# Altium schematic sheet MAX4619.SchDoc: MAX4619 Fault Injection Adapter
size B; Engineer: Joe Grand; Revision: A; SheetNumber: 1; SheetTotal: 1; PageSetup: Record=PageOptions¦CenterHorizontal=True¦CenterVertical=True¦PrintScale=0.70¦XCorrection=1.00¦YCorrection=1.00¦PrintKind=0¦BorderSize=5000000¦LeftOffset=0¦BottomOffset=0¦Orientation=2¦PaperLength=1000¦PaperWidth=1000¦Scale=100¦PaperSource=7¦PrintQuality=-4¦MediaType=1¦DitherType=10¦PrintScaleMode=1¦PaperKind=Letter
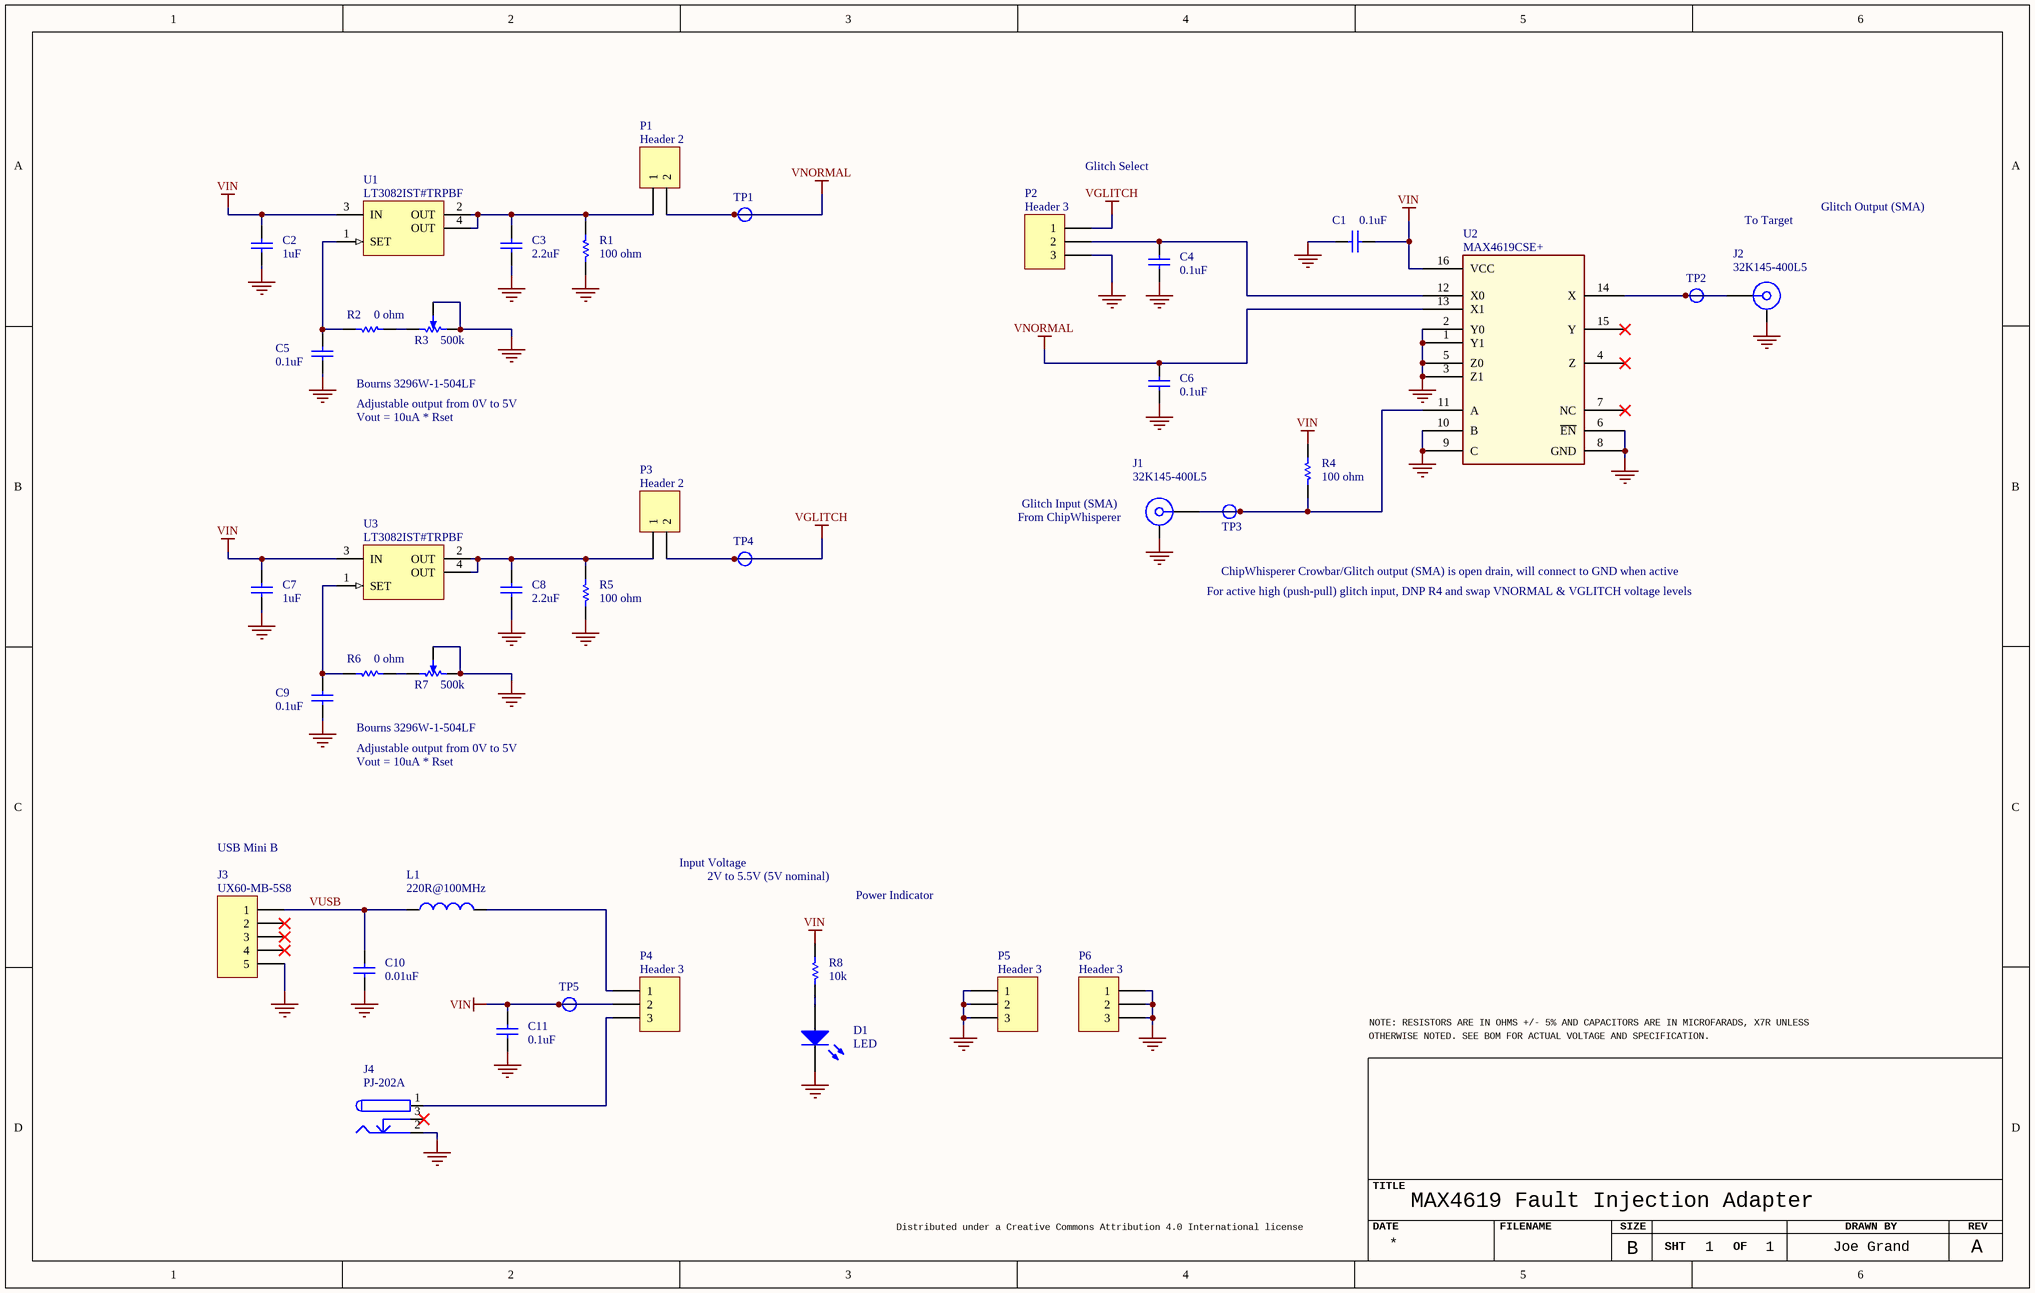
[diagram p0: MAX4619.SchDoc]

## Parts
*  Page Size: B  RevCode: A  Page Count: 1  OrgName: Joe Grand  Title: MAX4619 Fault Injection Adapter  (hidden comment: GIS Title Block)  (graphical)
C1  value 0.1uF  [CC2012-0805]  (hidden comment: Cap)
C2  value 1uF  [CC2012-0805]  (hidden comment: Cap)
C3  value 2.2uF  [CC2012-0805]  (hidden comment: Cap)
C4  value 0.1uF  [CC2012-0805]  (hidden comment: Cap)
C5  value 0.1uF  [CC2012-0805]  (hidden comment: Cap)
C6  value 0.1uF  [CC2012-0805]  (hidden comment: Cap)
C7  value 1uF  [CC2012-0805]  (hidden comment: Cap)
C8  value 2.2uF  [CC2012-0805]  (hidden comment: Cap)
C9  value 0.1uF  [CC2012-0805]  (hidden comment: Cap)
C10  value 0.01uF  [CC2012-0805]  (hidden comment: Cap)
C11  value 0.1uF  [CC2012-0805]  (hidden comment: Cap)
D1  LED  [CC2012-0805 LED]
J1  32K145-400L5  [ROS-32K145-400L5_V]
J2  32K145-400L5  [ROS-32K145-400L5_V]
J3  UX60-MB-5S8  [HRS UX60-MB-5S8 MINI-USB]
J4  PJ-202A  [PJ-202A-SLOTS]
L1  value 220R@100MHz  [CC2012-0805]  (hidden comment: Inductor)
P1  Header 2  [HEADER2]
P2  Header 3  [HEADER3]
P3  Header 2  [HEADER2]
P4  Header 3  [HEADER3]
P5  Header 3  [HEADER3]
P6  Header 3  [HEADER3]
R1  value 100 ohm  [CC2012-0805]  (hidden comment: Res1)
R2  value 0 ohm  [CC2012-0805]  (hidden comment: Res1)
R3  500k  [BOURNS-3296]
R4  value 100 ohm  [CC2012-0805]  (hidden comment: Res1)
R5  value 100 ohm  [CC2012-0805]  (hidden comment: Res1)
R6  value 0 ohm  [CC2012-0805]  (hidden comment: Res1)
R7  500k  [BOURNS-3296]
R8  value 10k  [CC2012-0805]  (hidden comment: Res1)
TP1  TESTPOINT  [TESTPOINT]  (value not drawn)
TP2  TESTPOINT  [TESTPOINT]  (value not drawn)
TP3  TESTPOINT  [TESTPOINT]  (value not drawn)
TP4  TESTPOINT  [TESTPOINT]  (value not drawn)
TP5  TESTPOINT  [TESTPOINT]  (value not drawn)
U1  LT3082IST#TRPBF  [LT-ST-3-SOT-223_M]
U2  MAX4619CSE+  [SO-G16]
U3  LT3082IST#TRPBF  [LT-ST-3-SOT-223_M]

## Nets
GND: C1.1 C2.1 C3.1 C4.1 C5.1 C6.1 C7.1 C8.1 C9.1 C10.1 C11.1 D1.2(K) J1.MP J2.MP J3.5 J4.2 P2.3 P5.1 P5.2 P5.3 P6.1 P6.2 P6.3 R1.2 R3.CW(+) R3.W R5.2 R7.CW(+) R7.W U2.1(Y1) U2.2(Y0) U2.3(Z1) U2.5(Z0) U2.6(~{EN}) U2.8(GND) U2.9(C) U2.10(B)
VGLITCH: P2.1 P3.2 TP4.1
VIN: C1.2 C2.2 C7.2 C11.2 P4.2 R4.1 R8.1 TP5.1 U1.3(IN) U2.16(VCC) U3.3(IN)
VNORMAL: C6.2 P1.2 TP1.1 U2.13(X1)
VUSB: C10.2 J3.1 L1.1
NetC3_2: C3.2 P1.1 R1.1 U1.2(OUT) U1.4(OUT)
NetC4_2: C4.2 P2.2 U2.12(X0)
NetC5_2: C5.2 R2.1 U1.1(SET)
NetC8_2: C8.2 P3.1 R5.1 U3.2(OUT) U3.4(OUT)
NetC9_2: C9.2 R6.1 U3.1(SET)
NetD1_1: D1.1(A) R8.2
NetJ1_1: J1.1 R4.2 TP3.1 U2.11(A)
NetJ2_1: J2.1 TP2.1 U2.14(X)
NetJ4_1: J4.1 P4.3
NetL1_2: L1.2 P4.1
NetR2_2: R2.2 R3.CCW(-)
NetR6_2: R6.2 R7.CCW(-)

Not connected (* = marked no-connect by the designer): J3 2* 3* 4*; J4 3*; U2 4(Z)* 7(NC)* 15(Y)*

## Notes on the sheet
- Glitch Select
- To Target
- Glitch Output (SMA)
- Vout = 10uA * Rset
- Bourns 3296W-1-504LF
- Adjustable output from 0V to 5V
- (near J1) Glitch Input (SMA)
- (near J1) From ChipWhisperer
- For active high (push-pull) glitch input, DNP R4 and swap VNORMAL & VGLITCH voltage levels
- ChipWhisperer Crowbar/Glitch output (SMA) is open drain, will connect to GND when active
- USB Mini B
- Input Voltage
- 2V to 5.5V (5V nominal)
- Power Indicator
- (near *) OTHERWISE NOTED. SEE BOM FOR ACTUAL VOLTAGE AND SPECIFICATION.
- (near *) NOTE: RESISTORS ARE IN OHMS +/- 5% AND CAPACITORS ARE IN MICROFARADS, X7R UNLESS
- Distributed under a Creative Commons Attribution 4.0 International license

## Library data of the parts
C1-C9 C11 = Cap: C0805C105K4RACTU
C10 = Cap: Capacitor
D1 = LED0: Typical LED
J1 J2 = 32K145-400L5: SMA Right Angle Jack, Edge Mount, Up to 18 GHz, -55 to 155 degC; Design Note 1: Footprint in library is a generic example - only application specific footprint delivers High Performance; Desgin Note 2: For more information about DRC setting, please look at following webpage, http://techdocs.altium.com/display/SCRT/Design+Rule+for+Edge-Mount+Connectors
J3 = Header 5: Header, 5-Pin
J4 = PWR JACK DC (PJ-202A): Low Voltage Power Supply Connector
L1 = Inductor: MPZ2012S221A
P1 P3 = Header 2: Header, 2-Pin
P2 P4-P6 = Header 3: Header, 3-Pin
R1 R2 R4-R6 R8 = Res1: Resistor
R3 R7 = RPot SM: Square Trimming Potentiometer
U1 U3 = LT3082IST#TRPBF: 200 mA Single Resistor Low Dropout Linear Regulator, 1.2 to 40 V Vin, Adjustable Vout, 3-pin SOT223 (ST-3), -40 to 125 degC, Pb-Free, Tape and Reel; Manufacturer: Linear Technology; Discrete Pass Element: no; Dropout Voltage(V): 1.3; Iout(mA): 200; Isupply(mA): 0.3; Noise(uV): 33; Number of Outputs: 1; Output Voltage: Adj; PSRR(dB): 90; Vin Max(V): 40; Vin Min(V): 1.2; Vout Max(V): 38.5; Vout Min(V): 0
U2 = MAX4619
